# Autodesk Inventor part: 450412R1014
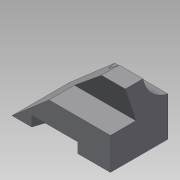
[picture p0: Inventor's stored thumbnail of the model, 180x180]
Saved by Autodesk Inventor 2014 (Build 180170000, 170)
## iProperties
Created: 2015-04
Part Number: 450412R1014
Material: Generic
Document SubType Name: Modeling
Designer: 203-11
Density: 1 g/cm^3
Appearance: Default
Author: 203-11
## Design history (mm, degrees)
sketch "스케치1"
  geometry: L1 (0, 0)-(79, 0); L2 (79, 0)-(79, 53.93); L3 (79, 89)-(44.733, 89); L4 (0, 89)-(0, 0); L5 (44.733, 89)-(0, 89); L6 (79, 53.93)-(79, 89); A1 r 44 centre (88, 97) between (44.733, 89) and (79, 53.93); A2 r 44 centre (88, 97) between (79, 53.93) and (44.733, 89); 1 further point
  constraints: 12 end point, 6 perpendicular, 4 point on circle, 2 centre point, 1 coincident, 1 horizontal
  dimensions: "d0" = 79 distance of L1.start L1.end; "d1" = 89 distance of L1.end L3.start; "d2" = 79 distance of L3.start L4.start; "d3" = 44 radius of A1; "d4" = 8 vertical distance of L3.start A1.centre; "d5" = 9 horizontal distance of A1.centre L3.start
extrude "돌출1" new body sketch "스케치1" distance "d7" = 135; taper "d8" = 0 deg
sketch "스케치2"
  geometry: L1 (0, 89)-(0, 0) reference; L2 (0, 0)-(135, 0) reference; L3 (0, 89)-(135, 89) reference; L4 (0, 0)-(102.383, 89); L5 (0, 0)-(0, 89); L6 (102.383, 89)-(0, 89)
  constraints: 6 end point, 2 collinear, 1 point on line
  dimensions: "d9" = 139 deg angle of L2 L4
extrude "돌출2" cut sketch "스케치2" stored distance "d10" = 135; taper "d11" = 0 deg
sketch "스케치4"
  geometry: L1 (-79, 0)-(-79, 62.04) reference; L2 (-79, 62.04)-(-79, 135) reference; L3 (0, 102.383)-(0, 0) reference; L4 (0, 0)-(0, 27); L5 (0, 27)-(-79, 52.669); L6 (0, 90.088)-(-79, 115.756); L7 (0, 27)-(0, 90.088); L8 (-79, 52.669)-(-79, 115.756)
  constraints: 10 end point, 4 point on line, 1 collinear, 1 parallel
  dimensions: "d12" = 27 distance of L3.end L4.end; "d13" = 72 deg angle of L3 L5; "d14" = 60 distance between parallel lines of L6 L5
extrude "돌출3" cut sketch "스케치4" distance "d15" = 14; taper "d16" = 0 deg
sketch "스케치6"
  geometry: L1 (44.733, 89)-(0, 89) reference; L2 (0, 89)-(0, 0) reference; L3 (0, 0)-(0, 44); L4 (0, 44)-(35, 44); L5 (35, 44)-(20.379, 89); L6 (20.379, 89)-(0, 89); L7 (0, 44)-(0, 89)
  constraints: 10 end point, 2 collinear, 2 point on line, 1 perpendicular
  dimensions: "d18" = 44 distance of L2.end L3.end; "d20" = 35 distance of L3.end L4.end; "d21" = 72 deg angle of L5 L4
extrude "돌출4" cut sketch "스케치6" stored distance "d22" = 14; taper "d23" = 0 deg
node "솔리드1"
